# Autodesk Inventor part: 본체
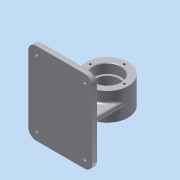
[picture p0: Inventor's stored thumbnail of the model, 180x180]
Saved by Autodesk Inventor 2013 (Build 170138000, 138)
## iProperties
Created: 2019-09
Part Number: 본체
Material: 알루미늄 6061
Document SubType Name: Modeling
Designer: Administrator
Density: 2.71 g/cm^3
Mass: 556.215 g
Surface Area: 496.983 cm^2
Volume: 205.245 cm^3
Author: Administrator
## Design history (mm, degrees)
sketch "스케치1"
  geometry: C1 r 32 at (0, 0); 1 further point
  constraints: 1 centre point, 1 coincident
  dimensions: "d0" = 64 diameter of C1
extrude "돌출1" new body sketch "스케치1" stored distance "d1" = 42; taper "d2" = 0 deg
sketch "스케치2"
  geometry: C1 r 32 at (0, 0) reference
hole "구멍1" sketch "스케치2" at (0, 0) diameter "d3" = 36; stored, may be unused: countersink angle "d7" = 90 deg, drill point angle "d9" = 118 deg; dims "d4" = 6, "d5" = 42, "d6" = 15, "d8" = 8
sketch "스케치3"
  geometry: C1 r 18 at (0, 0) reference; C2 r 32 at (0, 0) reference; C3 r 21 at (0, 0)
  constraints: 1 centre point, 1 coincident
  dimensions: "d10" = 42 diameter of C3
extrude "돌출2" cut sketch "스케치3" distance "d11" = 15; taper "d12" = 0 deg
sketch "스케치4"
  geometry: C1 r 21 at (0, 0) reference; 1 further point
  constraints: 1 vertical alignment
  dimensions: "d13" = 26 distance of C1.centre point (0, 26)
hole "구멍2" sketch "스케치4" at (0, 26) diameter "d14" = 3.242; stored, may be unused: countersink angle "d18" = 90 deg, drill point angle "d20" = 118 deg; dims "d15" = 8, "d16" = 42, "d17" = 15, "d19" = 10
sketch "스케치6"
  geometry: L1 (-62, -59)-(36, -59); L2 (36, -59)-(36, -50); L3 (36, -50)-(-62, -50); L4 (-62, -50)-(-62, -59); 1 further point
  constraints: 8 end point, 2 parallel, 1 horizontal, 1 perpendicular
  dimensions: "d30" = 59 distance from line of L1 point (0, 0); "d31" = 98 distance of L1.start L1.end; "d32" = 36 horizontal distance of L1.end point (0, 0); "d33" = 9 distance of L1.end L2.end
extrude "돌출4" join sketch "스케치6" stored distance "d34" = 126; taper "d35" = 0 deg
fillet "모깎기1" dims "d36" = 12
sketch "스케치8"
  geometry: L1 (24, -50)-(-50, -50) reference; L2 (24, -50)-(24, -59) reference; L3 (24, -50)-(-50, -50) reference; L4 (-50, -59)-(-50, -50) reference; L5 (-50, -59)-(24, -59) reference; L6 (24, -50)-(36, -50) reference; L7 (-32, 0)-(-32, -50); L8 (32, 0)-(32, -50); A1 r 32 centre (0, 0) between (-32, 0) and (32, 0) reference; 1 further point
  constraints: 4 end point, 2 perpendicular, 2 point on circle, 2 point on line, 2 tangent
extrude "돌출5" join sketch "스케치8" stored distance "d37" = 8; taper "d38" = 0 deg
sketch "스케치9"
  geometry: L1 (-12, -12)-(-12, -114) reference; L2 (54, -80)-(46, -80); L3 (46, -80)-(46, -46); L4 (46, -46)-(54, -46); L5 (54, -46)-(54, -80); L6 (46, -63)-(54, -63); 2 further points
  constraints: 10 end point, 2 midpoint, 2 parallel, 1 horizontal, 1 perpendicular
  dimensions: "d39" = 34 distance of L2.end L3.end; "d41" = 8 distance of L2.start L2.end; "d42" = 58 distance from line of L3.end L1; "d43" = 63 vertical distance of point (0, 0) L6.start
extrude "돌출6" join sketch "스케치9" stored distance "d44" = 8; taper "d45" = 0 deg
sketch "스케치10"
  geometry: A1 r 12 centre (74, -12) between (86, -12) and (74, 0) reference; A2 r 12 centre (0, -12) between (0, 0) and (-12, -12) reference; A3 r 12 centre (0, -114) between (-12, -114) and (0, -126) reference; A4 r 12 centre (74, -114) between (74, -126) and (86, -114) reference; 5 further points
  constraints: 4 coincident
hole "구멍3" sketch "스케치10" at (0, -12), (0, -114), (74, -114), (74, -12) diameter "d46" = 4.5; stored, may be unused: countersink angle "d50" = 90 deg, drill point angle "d52" = 118 deg; dims "d47" = 8, "d48" = 8, "d49" = 4.4, "d51" = 10
sketch "스케치11"
  geometry: L1 (-12, -12)-(-12, -114) reference; 3 further points
  constraints: 1 other
  dimensions: "d53" = 63 vertical distance of point (0, 0) point (-2, -63); "d54" = 10 distance from line of point (-2, -63) L1
feature "엠보싱1" sketch "스케치11" dims "d55" = 0.5, "d56" = 0
fillet "모깎기2" dims "d57" = 3
fillet "모깎기3" dims "d58" = 3
chamfer "모따기1" distance "d59" = 1; stored, may be unused: second distance "d60" = 2, angle "d61" = 45 deg
fillet "모깎기4" dims "d62" = 0.3
node "솔리드1"
pattern_circular "원형 패턴1" dims angle "d22" = 360 deg
mirror "대칭1"
node "투영된 루프1"
